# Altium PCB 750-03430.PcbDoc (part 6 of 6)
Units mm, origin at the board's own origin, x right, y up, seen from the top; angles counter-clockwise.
Board outline 141.61 x 63.5 mm, 6 copper layers (Top Layer, L2, L3, L4, L5, Bottom Layer), stack 1.557 mm thick; 401 components, 285 nets, 1356 pads, 1712 vias.
Unrouted connection lines stored in the file: 45.
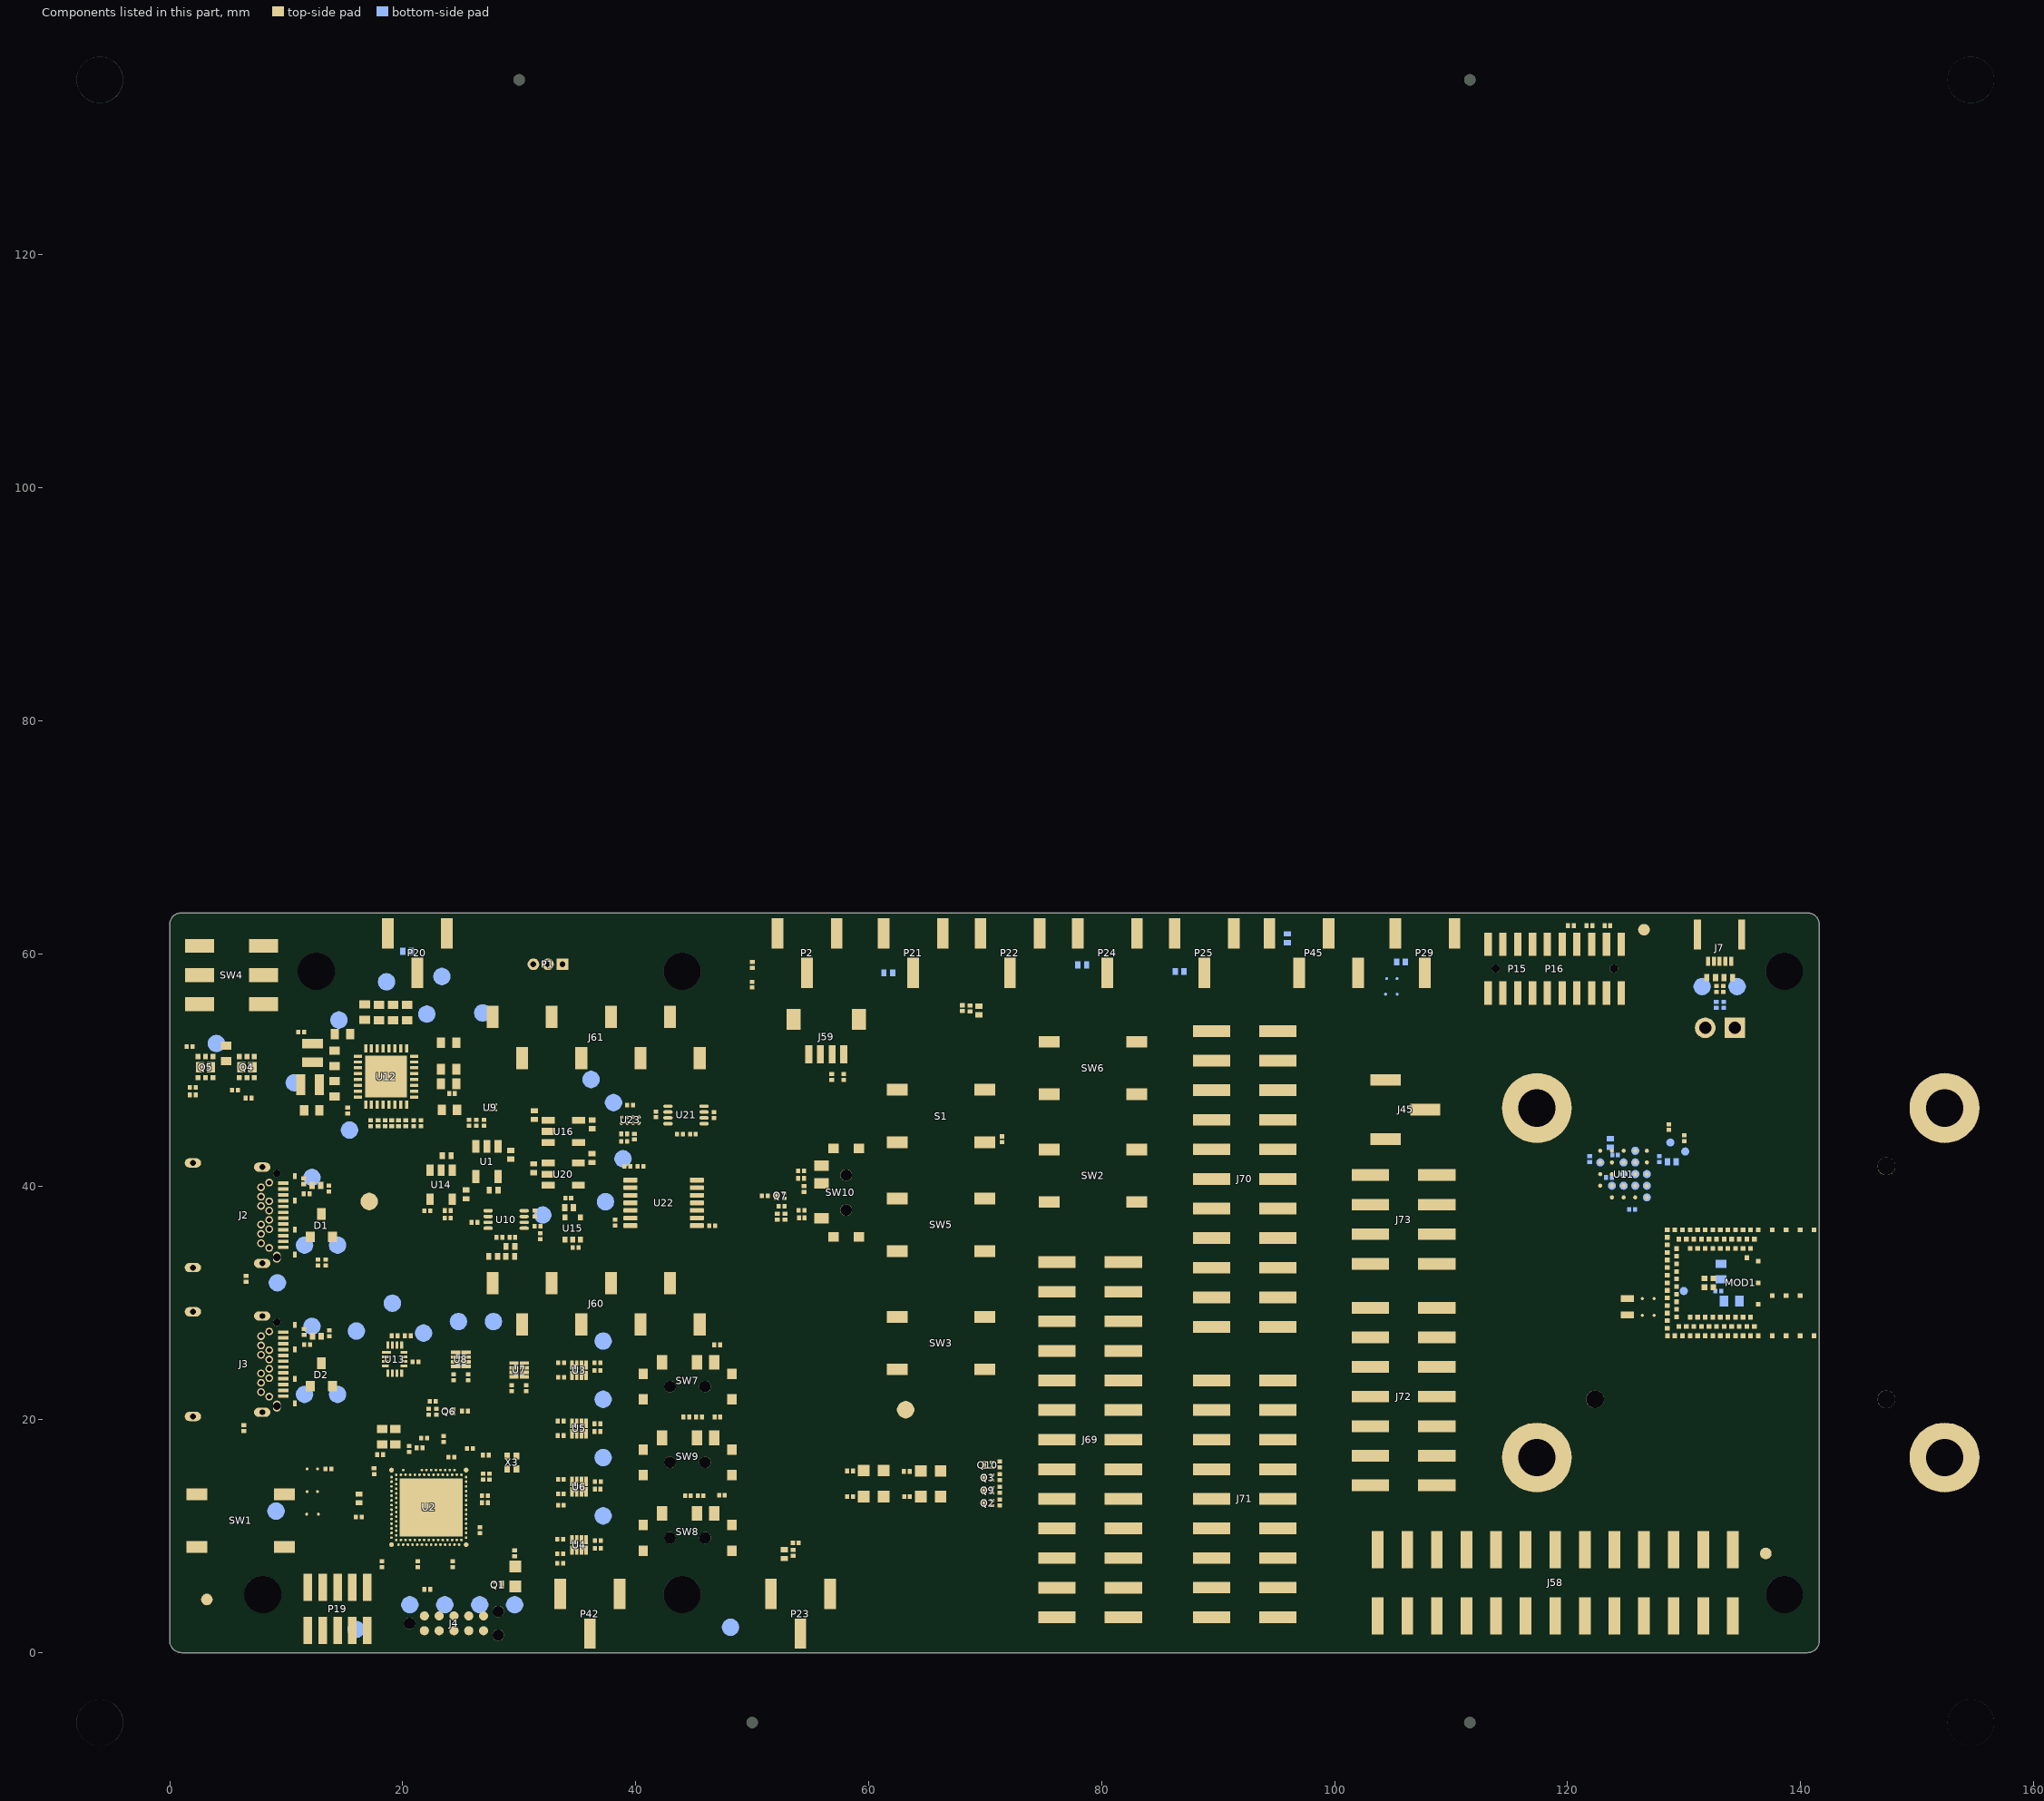
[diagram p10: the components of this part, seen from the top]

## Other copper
Top Layer:
  pour cut-out: 124.322,30.103 124.322,29.303 125.672,29.303 125.672,30.103
  pour cut-out: 112.607,59.562 125.175,59.562 125.175,62.07 112.607,62.07
  region net P3V3: 23.949,39.418 23.949,36.993 24.082,36.861 24.678,36.861 25.74,37.924 25.74,39.192 25.139,39.192 24.913,39.418
  region net P3V3: 33.735,37.118 33.053,37.8 33.053,39 33.262,39.209 34.141,39.209 34.141,37.118
  region net 5V0: 22.649,41.918 22.649,40.671 22.848,40.473 23.744,40.473 23.949,40.678 23.949,43.417 24.146,43.613 24.735,43.613 24.982,43.366 24.982,40.618 24.255,39.891 22.35,39.891 22.049,40.192 22.049,41.918
  region net 5V0: 25.982,44.023 25.982,42.24 26.241,41.981 28.064,41.981 28.975,42.892 29.576,42.892 29.576,43.937 29.49,44.023 27.886,44.023 27.886,42.923 27.601,42.639 26.866,42.639 26.582,42.923 26.582,44.023
  region net 5V0: 33.037,42.327 31.805,42.327 31.06,43.071 30.505,43.071 30.333,42.899 30.333,42.126 30.732,41.727 33.037,41.727
  region net 5V0: 33.046,45.994 30.429,45.994 30.288,45.853 30.288,45.453 30.433,45.309 31.861,45.309 31.946,45.394 33.046,45.394
  region net VBUS_DBGR: 12.776,26.859 12.776,27.461 13.389,27.461 13.501,27.349 13.903,27.349 13.903,26.374 13.747,26.219 13.416,26.219
  region net VBUS_nRF: 12.742,40.411 12.742,39.809 13.356,39.809 13.467,39.921 13.869,39.921 13.869,40.896 13.714,41.052 13.383,41.052
  region net NetC89_2: 11.335,27.447 11.335,27.095 11.575,26.854 12.48,26.854 12.48,27.985 12.379,28.086 12.045,28.086 11.987,28.027 11.987,27.573 11.861,27.447
  region net NetC88_2: 11.298,40.402 11.298,40.05 11.539,39.809 12.444,39.809 12.444,40.94 12.343,41.041 12.009,41.041 11.951,40.983 11.951,40.528 11.824,40.402
  region net VBUS_nRF: 2.141,49.578 2.045,49.482 2.045,47.081 2.132,46.994 2.542,46.994 2.635,47.088 2.635,49.578
  region net VBUS: 3.515,50.938 3.935,50.938 3.935,51.388 4.282,51.735 6.716,51.735 7.064,51.387 7.064,50.937 7.484,50.937 7.484,52.143 6.599,53.028 4.22,53.028 3.515,52.324
  region net NetQ4_3: 5.764,51.387 5.764,50.851 5.795,50.819 5.794,50.818 5.794,49.797 6.844,49.797 7.064,49.577 7.064,49.127 7.484,49.127 7.484,49.669 7.454,49.699 7.454,50.717 6.404,50.717 6.184,50.937 6.184,51.387
  region net VBUS_DBGR: 6.184,49.577 5.764,49.577 5.669,49.482 5.669,47.527 5.861,47.335 6.616,47.335 6.692,47.411 6.692,47.813 6.184,48.321
  region net NetQ5_3: 3.295,49.798 3.515,49.578 3.515,49.128 3.935,49.128 3.935,49.659 3.905,49.689 3.905,50.718 2.876,50.718 2.635,50.959 2.635,51.942 5.762,55.069 9.322,55.069 9.322,56.269 5.313,56.269 1.746,52.702 1.746,50.298 2.245,49.798
  region net VBUS: 23.649,49.565 23.649,50.475 23.649,51.61 22.824,51.61 22.824,50.75 21.909,49.835 20.924,49.835 20.924,49.565
  region net NetC5_1: 20.974,48.564 21.324,48.564 22.006,47.883 22.006,47.115 22.991,46.129 23.702,46.129 23.702,47.043 22.991,47.043 22.602,47.432 22.602,48.022 21.79,48.834 20.974,48.834 20.974,48.699
  region net 5V0: 23.649,49.335 23.649,48.425 23.649,47.235 23.024,47.235 22.824,47.435 22.824,48.15 21.909,49.065 20.924,49.065 20.924,49.335
  region net VOUT2: 11.644,49.657 11.644,47.344 11.894,47.094 11.894,46.093 10.967,46.093 10.844,46.215 10.844,49.657
  region net VOUT1: 13.599,53.665 14.674,53.665 14.874,53.465 14.87,53.461 14.87,52.869 15.124,52.615 15.874,52.615 15.874,53.765 14.86,54.779 12.795,54.779 11.981,53.965 11.374,53.358 11.374,51.875 13.174,51.875 13.174,53.24
  region net PVSS2: 16.174,48.834 15.609,48.834 14.874,48.099 13.692,48.099 13.692,47.618 13.085,47.01 12.504,47.01 12.504,46.097 14.271,46.097 14.674,46.499 14.674,47.374 15.864,48.564 16.174,48.564
  region net 5V0: 15.124,49.85 14.599,50.375 14.599,50.7 13.799,50.7 13.799,48.7 14.599,48.7 14.599,49.025 15.124,49.55
  region net PVSS1: 13.799,53.501 14.574,53.501 14.574,52.926 14.999,52.501 15.624,51.876 15.624,51.076 15.864,50.836 16.174,50.836 16.174,50.566 15.634,50.566 14.899,51.301 13.799,51.301
  pour cut-out: 140.563,30.925 140.563,28.869 140.665,28.869 140.665,28.462 140.563,28.462 140.563,27.295 141.609,27.295 141.609,30.925
  pour cut-out: 129.21,35.977 129.21,35.824 129.262,35.824 129.262,35.977
  pour cut-out: 128.882,34.999 129.035,34.999 129.035,34.947 128.882,34.947
  pour cut-out: 129.86,28.323 129.86,28.503 130.237,28.503 130.237,28.323
  pour cut-out: 129.86,27.523 129.86,27.676 129.912,27.676 129.912,27.523
  pour cut-out: 133.8,27.627 133.8,27.753 133.044,27.753 133.044,27.627
  pour cut-out: 132.081,28.323 132.081,28.476 132.134,28.476 132.134,28.323
  pour cut-out: 134.735,35.177 134.735,35.024 134.787,35.024 134.787,35.177
  pour cut-out: 136.034,35.177 136.034,35.024 135.981,35.024 135.981,35.177
  pour cut-out: 129.035,33.051 128.882,33.051 128.882,33.103 129.035,33.103
  region net NetC29_2: 132.909,28.6 132.909,29.468 133.066,29.625 133.396,29.625 133.538,29.482 133.538,29.229 133.309,29 133.309,28.6
  region net VDD_HV: 133.559,34.9 133.559,34.358 133.44,34.238 133.44,33.922 133.554,33.807 133.969,33.807 134.076,33.914 134.076,34.238 133.959,34.355 133.959,34.9
  text ".layer_Name" at 275.755,-33.955 h2.54
L2:
  pour cut-out: 140.563,30.925 140.563,28.869 140.665,28.869 140.665,28.462 140.563,28.462 140.563,27.295 141.609,27.295 141.609,30.925
  pour cut-out: 136.609,35.925 136.609,30.925 141.609,30.925 141.609,35.925
  pour cut-out: 11.476,11.1 13.021,11.1 13.021,14.841 13.021,16.554 11.476,16.554
  text ".layer_Name" at 275.755,-33.955 h2.54
L3:
  pour cut-out: 140.563,30.925 140.563,28.869 140.665,28.869 140.665,28.462 140.563,28.462 140.563,27.295 141.609,27.295 141.609,30.925
  pour cut-out: 136.609,35.925 136.609,30.925 141.609,30.925 141.609,35.925
  pour cut-out: 11.476,11.1 13.021,11.1 13.021,14.841 13.021,16.554 11.476,16.554
  text ".layer_Name" at 275.755,-33.955 h2.54
L4:
  rectangle net 5V0: 13.917,49.414 15.168,49.981
  pour cut-out: 140.563,30.925 140.563,28.869 140.665,28.869 140.665,28.462 140.563,28.462 140.563,27.295 141.609,27.295 141.609,30.925
  pour cut-out: 136.609,35.925 136.609,30.925 141.609,30.925 141.609,35.925
  text ".layer_Name" at 275.755,-33.955 h2.54
L5:
  pour cut-out: 140.563,30.925 140.563,28.869 140.665,28.869 140.665,28.462 140.563,28.462 140.563,27.295 141.609,27.295 141.609,30.925
  pour cut-out: 136.609,35.925 136.609,30.925 141.609,30.925 141.609,35.925
  text ".layer_Name" at 275.755,-33.955 h2.54
Bottom Layer:
  pour cut-out: 140.563,30.925 140.563,28.869 140.665,28.869 140.665,28.462 140.563,28.462 140.563,27.295 141.609,27.295 141.609,30.925
  pour cut-out: 136.609,35.925 136.609,30.925 141.609,30.925 141.609,35.925
  region net NetC29_2: 133.016,29.206 133.124,29.098 133.482,29.098 133.78,29.396 133.78,30.998 133.524,31.255 133.016,31.255
  text ".layer_Name" at 275.755,-33.955 h2.54

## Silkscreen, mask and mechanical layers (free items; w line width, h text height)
Top Overlay:
  drawing of 92 lines, arcs and shapes, not listed
  text "OFF" at 11.426,61.412 h1.27
  text "NFC" at 136.09,61.387 h1.8
  text "VDD_HV" at 27.234,57.813 h1.4 r90
  text "GND" at 24.198,57.045 h0.64 r90
  text "GND" at 57.66,57.045 h0.64 r90
  text "GND" at 66.767,57.045 h0.64 r90
  text "GND" at 75.081,57.045 h0.64 r90
  text "GND" at 83.44,57.045 h0.64 r90
  text "GND" at 91.754,57.045 h0.64 r90
  text "GND" at 110.696,57.045 h0.64 r90
  text "VDD_P9" at 89.074,55.287 h1.4
  text "P2.01" at 35.665,54.772 h0.7 r90
  text "ON" at 11.505,54.708 h1.27
  text "P2.09" at 40.737,54.681 h0.7 r90
  text "POWER" at 11.014,54.383 h1.8 r90
  text "GND" at 87.61,54.31 h0.64
  text "GND" at 95.705,54.31 h0.64
  text "P2.03" at 30.512,54.196 h0.7 r90
  text "VDD_P1" at 70.997,54.123 h1.4
  text "VDD_P7" at 77.711,54.084 h1.4
  text "VDD_P0" at 61.529,53.95 h1.4
  text "VDD_1V8" at 106.176,53.779 h1.4
  text "P2.02" at 29.312,53.643 h0.7 r90
  text "P2.00" at 34.453,53.619 h0.7 r90
  text "P2.08" at 39.556,53.596 h0.7 r90
  text "DEBUG IN TRACE" at 114.953,52.449 h1.8
  text "P2.01" at 95.673,51.688 h0.64
  text "VDD_HV" at 99.869,51.328 h1.27 r90
  text "VDD_HV'" at 103.411,51.328 h1.27 r90
  text "1V8_LDO" at 102.184,51.23 h1.27 r90
  text "VDD_1V8'" at 101.032,51.196 h1.27 r90
  text "BL54 Reset" at 61.279,49.809 h1.8
  text "P2.00" at 95.673,49.131 h0.64
  text "GND" at 108.292,48.902 h0.64
  text "RX" at 33.186,48.372 h0.7 r90
  text "TX" at 35.726,48.372 h0.7 r90
  text "5V" at 43.346,48.372 h0.7 r90
  text "INT" at 30.646,47.789 h0.7 r90
  text "PWM" at 28.106,47.673 h0.7 r90
  text "SCL" at 38.266,47.673 h0.7 r90
  text "SDA" at 40.806,47.673 h0.7 r90
  text "GND" at 45.886,47.673 h0.7 r90
  text "P2.02" at 95.673,46.608 h0.64
  text "P6.01" at 109.316,46.241 h0.64
  text "Button 3" at 75.072,44.671 h1.8
  text "LED, FLASH PWR LS ON" at 52.133,44.462 h1.52
  text "RXD" at 87.578,44.068 h0.64
  text "P2.04" at 95.673,44.068 h0.64
  text "P6.13" at 107.45,43.695 h0.64
  text "BL54H20 USB" at 0.566,43.608 h1.8
  text "ON" at 54.649,42.057 h0.64 r90
  text "RESET" at 108.948,41.896 h0.64
  text "CTS" at 87.578,41.511 h0.64
  text "P2.05" at 95.673,41.511 h0.64
  text "Button 2" at 62.079,40.492 h1.8
  text "nPM1300" at 14.056,40.032 h1.8
  text "SWDIO" at 108.948,39.371 h0.64
  text "TXD" at 87.578,38.979 h0.64
  text "P2.06" at 95.673,38.979 h0.64
  text "SWD" at 100.319,37.297 h0.89 r90
  text "UART0" at 86.433,37.268 h0.89 r90
  text "SWDCLK" at 108.948,36.746 h0.64
  text "RTS" at 87.578,36.364 h0.64
  text "P2.07" at 95.673,36.364 h0.64
  text "Button 0" at 75.203,35.639 h1.8
  text "GND" at 16.307,35.561 h1.4
  text "OFF" at 54.695,34.965 h0.64 r90
  text "GND" at 81.885,34.381 h0.64
  text "GND" at 73.602,34.322 h0.64
  text "GND" at 108.948,34.238 h0.64
  text "RX" at 87.578,33.899 h0.64
  text "P2.09" at 95.673,33.899 h0.64
  text "SCK" at 36.694,33.204 h0.7 r90
  text "MOSI" at 40.766,33.203 h0.7 r90
  text "MISO" at 38.226,33.177 h0.7 r90
  text "3V3" at 43.306,33.154 h0.7 r90
  text "GND" at 45.846,33.159 h0.7 r90
  text "CS" at 33.146,33.115 h0.7 r90
  text "UI0" at 73.602,31.92 h0.64
  text "AN" at 29.361,31.847 h0.7 r90
  text "P0.08" at 81.885,31.845 h0.64
  text "RST" at 30.705,31.378 h0.7 r90
  text "TX" at 87.578,31.284 h0.64
  text "P2.08" at 95.673,31.284 h0.64
  text "Button 1" at 62.079,30.645 h1.8
  text "P9.05" at 109.263,30.512 h0.64
  text "DEBUGGER" at 0.389,29.83 h1.8
  text "MK_UART" at 86.181,29.827 h0.64 r90
  text "UI3" at 73.602,29.363 h0.64
  text "P0.11" at 81.885,29.32 h0.64
  text "INT" at 87.684,28.742 h0.64
  text "P2.03" at 95.673,28.742 h0.64
  text "P9.04" at 109.263,27.987 h0.64
  text "UI2" at 73.602,26.831 h0.64
  text "P0.10" at 81.902,26.811 h0.64
  text "OFF" at 47.767,26.123 h0.64
  text "ON" at 40.618,26.093 h0.64
  text "P1.01" at 29.421,25.509 h0.64 r90
  text "P7.00" at 34.518,25.475 h0.64 r90
  text "P9.00" at 109.263,25.432 h0.64
  text "P7.02" at 39.57,25.415 h0.64 r90
  text "UI0" at 101.323,25.38 h0.64
  text "MK" at 86.247,25.107 h0.89 r90
  text "PWM" at 86.826,25.039 h0.64
  text "P1.02" at 32.85,24.895 h0.64 r90
  text "P7.01" at 38.301,24.823 h0.64 r90
  text "Button" at 72.762,24.728 h0.89 r90
  text "P1.00" at 28.243,24.572 h0.64 r90
  text "UI1" at 73.602,24.212 h0.64
  text "P0.09" at 81.855,24.216 h0.64
  text "SWD0 LS" at 49.067,24.191 h1.8
  text "DATA1" at 86.804,24.145 h0.64
  text "P7.05" at 95.673,24.148 h0.64
  text "MOD1" at 126.391,23.757 h1.8
  text "P9.02" at 109.263,22.907 h0.64
  text "UI2" at 101.323,22.856 h0.64
  text "P0.05" at 81.885,21.685 h0.64
  text "P7.07" at 95.673,21.673 h0.64
  text "DATA3" at 86.826,21.473 h0.64
  text "P9.01" at 109.263,20.398 h0.64
  text "UI1" at 101.535,20.231 h0.64
  text "GND" at 64.431,19.872 h1.4
  text "OFF" at 47.942,19.753 h0.64
  text "ON" at 40.686,19.686 h0.64
  text "P0.07" at 81.885,19.16 h0.64
  text "LEDS" at 100.249,19.132 h0.89 r90
  text "DATA2" at 87.023,19.122 h0.64
  text "P7.06" at 95.673,19.122 h0.64
  text "Debugger" at 24.556,18.048 h1.8
  text "P9.03" at 109.263,17.803 h0.64
  text "UI3" at 101.323,17.646 h0.64
  text "UART1 LS" at 49.071,17.573 h1.8
  text "LED1" at 58.357,17.328 h1.14
  text "LED3" at 63.574,17.328 h1.14
  text "P0.06" at 81.902,16.651 h0.64
  text "CLK" at 88.293,16.587 h0.64
  text "P7.03" at 95.639,16.587 h0.64
  text "Trace" at 86.227,16.507 h0.89 r90
  text "RESET" at 3.223,15.375 h1.8
  text "GND" at 109.263,15.223 h0.64
  text "GND" at 101.217,15.163 h0.64
  text "DATA0" at 87.039,14.112 h0.64
  text "P0.01" at 81.722,14.067 h0.64
  text "P7.04" at 95.673,14.061 h0.64
  text "ON" at 40.68,13.144 h0.64
  text "OFF" at 48.157,13.114 h0.64
  text "CS" at 86.418,12.215 h0.64
  text "P0.02" at 81.885,11.525 h0.64
  text "P7.01" at 95.673,11.513 h0.64
  text "MOSI" at 87.885,11.423 h0.64
  text "LED2" at 58.357,10.525 h1.14
  text "LED0" at 63.574,10.525 h1.14
  text "UART0 LS" at 49.133,10.462 h1.8
  text "P0.03" at 81.885,9 h0.64
  text "P7.02" at 95.673,8.981 h0.64
  text "CLK" at 88.308,8.933 h0.64
  text "P1.11" at 102.824,8.816 h0.64 r90
  text "P1.10" at 105.349,8.816 h0.64 r90
  text "P1.09" at 107.858,8.816 h0.64 r90
  text "P1.07" at 110.453,8.816 h0.64 r90
  text "P1.08" at 112.983,8.815 h0.64 r90
  text "P1.06" at 115.508,8.815 h0.64 r90
  text "P1.05" at 118.017,8.815 h0.64 r90
  text "P1.04" at 120.612,8.815 h0.64 r90
  text "P1.00" at 125.795,8.815 h0.64 r90
  text "P1.01" at 128.32,8.815 h0.64 r90
  text "GND" at 133.393,8.815 h0.64 r90
  text "P1.03" at 123.21,8.805 h0.64 r90
  text "P1.02" at 130.772,8.764 h0.64 r90
  text "MK_SPI" at 86.422,6.761 h0.89 r90
  text "750-03430-R3.0" at 60.111,6.716 h1.65
  text "P0.00" at 81.902,6.491 h0.64
  text "P7.00" at 95.673,6.368 h0.64
  text "MISO" at 87.779,6.335 h0.64
  text "VDD_SWDO" at 32.394,6.038 h1.52 r90
  text "DVK-BL54H20" at 59.674,5.233 h1.65
  text "P0.04" at 81.855,3.896 h0.64
  text "GND" at 88.293,3.808 h0.64
  text "GND" at 95.676,3.808 h0.64
  text "AN" at 125.705,1.947 h0.64 r90
  text "SCL" at 123.246,1.799 h0.64 r90
  text "SDA" at 120.615,1.749 h0.64 r90
  text "TXD" at 102.724,1.312 h0.64 r90
  text "RXD" at 105.281,1.312 h0.64 r90
  text "RTS" at 107.813,1.312 h0.64 r90
  text "CTS" at 110.432,1.312 h0.64 r90
  text "RST" at 128.245,1.312 h0.64 r90
  text "UART1" at 97.332,1.195 h0.89
  text "MK" at 138.001,1.094 h0.64
  text "VDD_P2" at 49.896,0.618 h1.4 r90
  text "I2C" at 121.922,0.604 h0.64
  text "DEBUG OUT" at 2.116,0.355 h1.8
  text "GND" at 38.932,0.209 h0.64 r90
  text ".layer_Name" at 275.755,-33.955 h2.54
Bottom Overlay:
  text ".layer_Name" at 275.755,-33.955 h2.54
Top Paste:
  text ".layer_Name" at 275.755,-33.955 h2.54
Bottom Paste:
  text ".layer_Name" at 275.755,-33.955 h2.54
Top Solder:
  region: 140.959,27 140.959,27.295 140.908,27.295 140.908,27.451 141.41,27.451 141.41,27 141.359,27
  region: 140.959,27.4 141.254,27.4 141.254,27.451 141.41,27.451 141.41,26.949 141.35,26.949 141.35,27 140.959,27
  text ".layer_Name" at 275.755,-33.955 h2.54
Bottom Solder:
  text ".layer_Name" at 275.755,-33.955 h2.54
Board Outline:
  lines w0.254: 0,62.482 cw(c1.016,62.482) 1.016,63.498 ; 0,62.484 0,1.016 ccw(c1.016,1.016) 1.016,0 140.593,0 ccw(c140.593,1.016) 141.609,1.016 141.609,62.484 ccw(c140.593,62.484) 140.593,63.5 1.02,63.5
Top Title Block:
  drawing of 49 lines, arcs and shapes, not listed
  text "DATE" at 367.388,235.868 h1.78
  text "ENG." at 381.993,235.639 h1.78
  text "REV." at 271.528,235.614 h1.78
  text "DESCRIPTION" at 306.86,235.614 h1.78
  text "1.0" at 271.558,231.69 h1.78
  text "Sep 13, 2023" at 362.245,231.69 h1.78
  text "Initial release" at 279.658,231.605 h1.78
  text "2.0" at 271.559,227.502 h1.78
  text "Jun 18, 2024" at 362.246,227.502 h1.78
  text "DVT1" at 279.659,227.418 h1.78
  text "3.0" at 271.56,223.315 h1.78
  text "Oct 15, 2024" at 362.248,223.315 h1.78
  text "Add R121, R122 and R123" at 279.66,223.23 h1.78
  text "APPROVALS" at 278.295,0.335 h1.78
  text "DATE" at 306.235,0.335 h1.78
  text "DRAWN:" at 270.675,-4.745 h1.27
  text ".ProjectDrawnBy" at 283.375,-4.745 h1.27
  text ".ProjectDrawnDate" at 303.695,-4.745 h1.27
  text ".ProjectAddress1" at 359.575,-4.745 h1.52
  text ".ProjectAddress2" at 359.575,-7.285 h1.52
  text "CHECKED:" at 270.675,-9.825 h1.27
  text ".ProjectCheckedBy" at 283.375,-9.825 h1.27
  text ".ProjectCheckedDate" at 303.695,-9.825 h1.27
  text "Phone: .ProjectPhone" at 359.575,-9.825 h1.52
  text "www.ezurio.com" at 359.575,-12.365 h1.52
  text "APPROVED:" at 270.675,-14.905 h1.27
  text ".ProjectApprovedBy" at 283.375,-14.905 h1.27
  text ".ProjectApprovedDate" at 303.695,-14.905 h1.27
  text "Title:" at 270.222,-20.056 h1.27
  text "PCB, .ProjectTitle" at 273.722,-24.856 h3.81
  text ", Chip Antenna" at 361.638,-25.083 h3.81
  text "Layer:" at 270.722,-29.956 h1.27
  text "Project:" at 322.745,-30.145 h1.27
  text "DWG NO." at 350.685,-30.145 h1.27
  text "REV:" at 382.435,-30.145 h1.27
  text ".ProjectPCBRevision" at 382.435,-32.685 h1.78
  text "'.ProjectPCBNumber'" at 357.543,-33.61 h1.78
  text ".ProjectNumber" at 329.095,-33.955 h1.52
  text "Customer: .ProjectCustomerName" at 303.695,-37.765 h1.27
  text "Last Modified:" at 324.015,-37.765 h1.27
  text "SIZE:" at 350.685,-37.765 h1.27
  text "SCALE:" at 360.337,-37.765 h1.27
  text "SHEET:" at 372.275,-37.765 h1.27
  text "File:" at 270.268,-37.878 h1.27
  text ".PCB_File_Name_No_Path" at 272.422,-39.956 h1.27
  text "'.Print_Date'" at 324.015,-40.305 h1.27
  text ".Print_Time" at 335.445,-40.305 h1.27
  text "1:1" at 362.115,-40.813 h1.27
  text "1 OF 1" at 375.831,-40.813 h1.27
  text "B" at 351.701,-41.829 h3.05
Top Assembly (Mech13):
  text ".layer_Name" at 275.755,-33.955 h2.54
Bottom Assembly (Mech14):
  text ".layer_Name" at 275.755,-33.955 h2.54
Drill Drawing:
  drawing of 264 lines, arcs and shapes, not listed
  text "PCB NOTES:" at 205.903,187.993 h3.97
  text "1. Thickness: 1.6mm, Tolerance+/-0.1mm / 2. Impedance= (1) RF 50 ohm, Traces-TOP/L3 Layer ref to L2/L2, L4 Layer, Trace Width 5/4mil. /   Differential = (2) 90 ohm, Traces-TOP/ BOT Layer ref to L2/ L5 Layer, Trace Width 4.7mil, Spacing 4mil / 3. Please refer to the \"PCB SPECIFICATION SHEET\" for details." at 205.277,170.262 h1.52
  text "Symbol" at 201.704,153.404 h1.83
  text "Count" at 214.553,153.404 h1.83
  text "Hole Size" at 231.059,153.404 h1.83
  text "Plated" at 260.26,153.404 h1.83
  text "Hole Type" at 273.109,153.404 h1.83
  text "Drill Layer Pair" at 291.748,153.404 h1.83
  text "Via/Pad" at 329.836,153.404 h1.83
  text "Pad Shape" at 344.819,153.404 h1.83
  text "223" at 214.553,149.594 h1.52
  text "7.87mil (0.200mm)" at 231.059,149.594 h1.52
  text "PTH" at 260.26,149.594 h1.52
  text "Round" at 273.109,149.594 h1.52
  text "Top Layer - Bottom Layer" at 291.748,149.594 h1.52
  text "Via" at 329.836,149.594 h1.52
  text "Rounded" at 344.819,149.594 h1.52
  text "1306" at 214.553,145.784 h1.52
  text "9.84mil (0.250mm)" at 231.059,145.784 h1.52
  text "PTH" at 260.26,145.784 h1.52
  text "Round" at 273.109,145.784 h1.52
  text "Top Layer - Bottom Layer" at 291.748,145.784 h1.52
  text "Via" at 329.836,145.784 h1.52
  text "Rounded" at 344.819,145.784 h1.52
  text "16" at 214.553,141.974 h1.52
  text "12.00mil (0.305mm)" at 231.059,141.974 h1.52
  text "PTH" at 260.26,141.974 h1.52
  text "Round" at 273.109,141.974 h1.52
  text "Top Layer - Bottom Layer" at 291.748,141.974 h1.52
  text "Via" at 329.836,141.974 h1.52
  text "Rounded" at 344.819,141.974 h1.52
  text "9" at 214.553,138.164 h1.52
  text "12.01mil (0.305mm)" at 231.059,138.164 h1.52
  text "PTH" at 260.26,138.164 h1.52
  text "Round" at 273.109,138.164 h1.52
  text "Top Layer - Bottom Layer" at 291.748,138.164 h1.52
  text "Via" at 329.836,138.164 h1.52
  text "Rounded" at 344.819,138.164 h1.52
  text "24" at 214.553,134.354 h1.52
  text "15.75mil (0.400mm)" at 231.059,134.354 h1.52
  text "PTH" at 260.26,134.354 h1.52
  text "Round" at 273.109,134.354 h1.52
  text "Top Layer - Bottom Layer" at 291.748,134.354 h1.52
  text "Pad" at 329.836,134.354 h1.52
  text "Rounded" at 344.819,134.354 h1.52
  text "A" at 200.965,134.1 h1.69
  text "3" at 214.553,130.544 h1.52
  text "19.69mil (0.500mm)" at 231.059,130.544 h1.52
  text "PTH" at 260.26,130.544 h1.52
  text "Round" at 273.109,130.544 h1.52
  text "Top Layer - Bottom Layer" at 291.748,130.544 h1.52
  text "Pad" at 329.836,130.544 h1.52
  text "(Mixed)" at 344.819,130.544 h1.52
  text "G" at 200.965,130.29 h1.69
  text "8" at 214.553,126.734 h1.52
  text "19.69mil (0.500mm)" at 231.059,126.734 h1.52
  text "PTH" at 260.26,126.734 h1.52
  text "Slot" at 273.109,126.734 h1.52
  text "Top Layer - Bottom Layer" at 291.748,126.734 h1.52
  text "Pad" at 329.836,126.734 h1.52
  text "Rounded" at 344.819,126.734 h1.52
  text "B" at 200.965,126.48 h1.69
  text "2" at 214.553,122.924 h1.52
  text "25.59mil (0.650mm)" at 231.059,122.924 h1.52
  text "NPTH" at 260.26,122.924 h1.52
  text "Round" at 273.109,122.924 h1.52
  text "Top Layer - Bottom Layer" at 291.748,122.924 h1.52
  text "Pad" at 329.836,122.924 h1.52
  text "Rounded" at 344.819,122.924 h1.52
  text "C" at 200.965,122.67 h1.69
  text "2" at 214.553,119.114 h1.52
  text "25.59mil (0.650mm)" at 231.059,119.114 h1.52
  text "NPTH" at 260.26,119.114 h1.52
  text "Slot" at 273.109,119.114 h1.52
  text "Top Layer - Bottom Layer" at 291.748,119.114 h1.52
  text "Pad" at 329.836,119.114 h1.52
  text "Rounded" at 344.819,119.114 h1.52
  text "D" at 200.965,118.86 h1.69
  text "2" at 214.553,115.304 h1.52
  text "27.56mil (0.700mm)" at 231.059,115.304 h1.52
  text "NPTH" at 260.26,115.304 h1.52
  text "Round" at 273.109,115.304 h1.52
  text "Top Layer - Bottom Layer" at 291.748,115.304 h1.52
  text "Pad" at 329.836,115.304 h1.52
  text "Rounded" at 344.819,115.304 h1.52
  text "3" at 214.553,111.494 h1.52
  text "39.00mil (0.991mm)" at 231.059,111.494 h1.52
  text "NPTH" at 260.26,111.494 h1.52
  text "Round" at 273.109,111.494 h1.52
  text "Top Layer - Bottom Layer" at 291.748,111.494 h1.52
  text "Pad" at 329.836,111.494 h1.52
  text "Rounded" at 344.819,111.494 h1.52
  text "8" at 214.553,107.684 h1.52
  text "39.37mil (1.000mm)" at 231.059,107.684 h1.52
  text "NPTH" at 260.26,107.684 h1.52
  text "Round" at 273.109,107.684 h1.52
  text "Top Layer - Bottom Layer" at 291.748,107.684 h1.52
  text "Pad" at 329.836,107.684 h1.52
  text "Rounded" at 344.819,107.684 h1.52
  text "2" at 214.553,103.874 h1.52
  text "42.00mil (1.067mm)" at 231.059,103.874 h1.52
  text "PTH" at 260.26,103.874 h1.52
  text "Round" at 273.109,103.874 h1.52
  text "Top Layer - Bottom Layer" at 291.748,103.874 h1.52
  text "Pad" at 329.836,103.874 h1.52
  text "Rounded" at 344.819,103.874 h1.52
  text "3" at 214.553,100.064 h1.52
  text "60.00mil (1.524mm)" at 231.059,100.064 h1.52
  text "NPTH" at 260.26,100.064 h1.52
  text "Round" at 273.109,100.064 h1.52
  text "Top Layer - Bottom Layer" at 291.748,100.064 h1.52
  text "Pad" at 329.836,100.064 h1.52
  text "Rounded" at 344.819,100.064 h1.52
  text "4" at 214.553,96.254 h1.52
  text "125.98mil (3.200mm)" at 231.059,96.254 h1.52
  text "NPTH" at 260.26,96.254 h1.52
  text "Round" at 273.109,96.254 h1.52
  text "Top Layer - Bottom Layer" at 291.748,96.254 h1.52
  text "Pad" at 329.836,96.254 h1.52
  text "Rounded" at 344.819,96.254 h1.52
  text "6" at 214.553,92.444 h1.52
  text "126.00mil (3.200mm)" at 231.059,92.444 h1.52
  text "NPTH" at 260.26,92.444 h1.52
  text "Round" at 273.109,92.444 h1.52
  text "Top Layer - Bottom Layer" at 291.748,92.444 h1.52
  text "Pad" at 329.836,92.444 h1.52
  text "Rounded" at 344.819,92.444 h1.52
  text "4" at 214.553,88.634 h1.52
  text "157.48mil (4.000mm)" at 231.059,88.634 h1.52
  text "NPTH" at 260.26,88.634 h1.52
  text "Round" at 273.109,88.634 h1.52
  text "Top Layer - Bottom Layer" at 291.748,88.634 h1.52
  text "Pad" at 329.836,88.634 h1.52
  text "Rounded" at 344.819,88.634 h1.52
  text "Symbol" at 201.704,87.365 h1.83
  text "Symbol" at 201.704,87.365 h1.83
  text "Count" at 214.553,87.365 h1.83
  text "Count" at 214.553,87.365 h1.83
  text "Hole Size" at 228.012,87.365 h1.83
  text "Hole Size" at 229.281,87.365 h1.83
  text "Plated" at 254.166,87.365 h1.83
  text "Plated" at 255.436,87.365 h1.83
  text "Hole Type" at 267.015,87.365 h1.83
  text "Hole Type" at 268.285,87.365 h1.83
  text "Drill Layer Pair" at 285.654,87.365 h1.83
  text "Drill Layer Pair" at 286.923,87.365 h1.83
  text "Via/Pad" at 315.871,87.365 h1.83
  text "Via/Pad" at 317.141,87.365 h1.83
  text "Pad Shape" at 330.853,87.365 h1.83
  text "Pad Shape" at 332.123,87.365 h1.83
  text "1625 Total" at 214.553,84.824 h1.52
  text "41" at 214.553,83.555 h1.52
  text "117" at 214.553,83.555 h1.52
  text "3.94mil (0.100mm)" at 228.012,83.555 h1.52
  text "3.94mil (0.100mm)" at 229.281,83.555 h1.52
  text "PTH" at 254.166,83.555 h1.52
  text "PTH" at 255.436,83.555 h1.52
  text "Round" at 267.015,83.555 h1.52
  text "Round" at 268.285,83.555 h1.52
  text "Top Layer - L2" at 285.654,83.555 h1.52
  text "Top Layer - L3" at 286.923,83.555 h1.52
  text "Via" at 315.871,83.555 h1.52
  text "Via" at 317.141,83.555 h1.52
  text "Rounded" at 330.853,83.555 h1.52
  text "Rounded" at 332.123,83.555 h1.52
  text "Slot definitions :" at 201.704,81.142 h1.52
  text "Routed Path Length" at 227.934,81.142 h1.52
  text "= Calculated from tool start centre position to tool end centre position." at 255.942,81.142 h1.52
  text "41 Total" at 214.553,79.745 h1.52
  text "117 Total" at 214.553,79.745 h1.52
  text "Hole Length" at 227.934,78.602 h1.52
  text "= Routed Path Length + Tool Size = Slot length as defined in the PCB layout" at 245.531,78.602 h1.52
  text "Layer" at 204.821,61.27 h1.52
  text "Name" at 215.233,61.27 h1.52
  text "Material" at 238.849,61.27 h1.52
  text "Thickness" at 254.085,61.27 h1.52
  text "Constant" at 270.591,61.27 h1.52
  text "Top Overlay" at 215.233,58.222 h1.52
  text "Top Solder" at 215.233,55.174 h1.52
  text "SM-003" at 238.849,55.174 h1.52
  text "0.40mil" at 254.085,55.174 h1.52
  text "3.5" at 270.591,55.174 h1.52
  text "1" at 204.821,52.126 h1.52
  text "Top Layer" at 215.233,52.126 h1.52
  text "CF-002" at 238.849,52.126 h1.52
  text "1.89mil" at 254.085,52.126 h1.52
  text "Dielectric 1" at 215.233,49.078 h1.52
  text "PP-010" at 238.849,49.078 h1.52
  text "3.31mil" at 254.085,49.078 h1.52
  text "4" at 270.591,49.078 h1.52
  text "2" at 204.821,46.03 h1.52
  text "L2" at 215.233,46.03 h1.52
  text "CF-002" at 238.849,46.03 h1.52
  text "1.18mil" at 254.085,46.03 h1.52
  text "Dielectric 2" at 215.233,42.982 h1.52
  text "PP-010" at 238.849,42.982 h1.52
  text "3.19mil" at 254.085,42.982 h1.52
  text "4" at 270.591,42.982 h1.52
  text "3" at 204.821,39.934 h1.52
  text "L3" at 215.233,39.934 h1.52
  text "CF-002" at 238.849,39.934 h1.52
  text "1.58mil" at 254.085,39.934 h1.52
  text "Dielectric 3" at 215.233,36.886 h1.52
  text "Core-042" at 238.849,36.886 h1.52
  text "39.02mil" at 254.085,36.886 h1.52
  text "4.6" at 270.591,36.886 h1.52
  text "4" at 204.821,33.838 h1.52
  text "L4" at 215.233,33.838 h1.52
  text "CF-002" at 238.849,33.838 h1.52
  text "1.58mil" at 254.085,33.838 h1.52
  text "Dielectric 4" at 215.233,30.79 h1.52
  text "PP-010" at 238.849,30.79 h1.52
  text "3.19mil" at 254.085,30.79 h1.52
  text "4" at 270.591,30.79 h1.52
  text "5" at 204.821,27.742 h1.52
  text "L5" at 215.233,27.742 h1.52
  text "CF-002" at 238.849,27.742 h1.52
  text "1.18mil" at 254.085,27.742 h1.52
  text "Dielectric 5" at 215.233,24.694 h1.52
  text "PP-010" at 238.849,24.694 h1.52
  text "3.31mil" at 254.085,24.694 h1.52
  text "4" at 270.591,24.694 h1.52
  text "6" at 204.821,21.646 h1.52
  text "Bottom Layer" at 215.233,21.646 h1.52
  text "CF-002" at 238.849,21.646 h1.52
  text "1.89mil" at 254.085,21.646 h1.52
  text "Bottom Solder" at 215.233,18.598 h1.52
  text "SM-003" at 238.849,18.598 h1.52
  text "0.40mil" at 254.085,18.598 h1.52
  text "3.5" at 270.591,18.598 h1.52
  text "Bottom Overlay" at 215.233,15.55 h1.52
Panel:
  lines w0.254: -1.996,13.22 cw(c-0.998,13.22) -0.998,14.218 cw(c-0.998,13.22) -0.001,13.22 ; -1.996,17.215 ccw(c-0.998,17.215) -0.998,16.218 ccw(c-0.998,17.215) -0.001,17.215 ; -1.996,46.285 cw(c-0.998,46.285) -0.998,47.282 cw(c-0.998,46.285) -0.001,46.285 ; -1.996,50.28 ccw(c-0.998,50.28) -0.998,49.282 ccw(c-0.998,50.28) -0.001,50.28 ; -1.996,78.72 cw(c-0.998,78.72) -0.998,79.718 cw(c-0.998,78.72) -0.001,78.72 ; -1.996,82.715 ccw(c-0.998,82.715) -0.998,81.718 ccw(c-0.998,82.715) -0.001,82.715 ; -1.996,111.785 cw(c-0.998,111.785) -0.998,112.782 cw(c-0.998,111.785) -0.001,111.785 ; -1.996,115.78 ccw(c-0.998,115.78) -0.998,114.782 ccw(c-0.998,115.78) -0.001,115.78 ; 15.206,-1.995 ccw(c15.206,-0.998) 16.204,-0.998 ccw(c15.206,-0.998) 15.206,0 ; 15.206,63.505 ccw(c15.206,64.502) 16.204,64.502 ccw(c15.206,64.502) 15.206,65.5 ; 15.206,129.005 ccw(c15.206,130.002) 16.204,130.002 ccw(c15.206,130.002) 15.206,131 ; 19.202,-1.995 cw(c19.202,-0.998) 18.204,-0.998 cw(c19.202,-0.998) 19.202,0 ; 19.202,63.505 cw(c19.202,64.502) 18.204,64.502 cw(c19.202,64.502) 19.202,65.5 ; 19.201,129.005 cw(c19.201,130.002) 18.204,130.002 cw(c19.201,130.002) 19.201,131 ; 68.809,-1.998 ccw(c68.809,-1) 69.807,-1 ccw(c68.809,-1) 68.809,-0.002 ; 68.809,63.502 ccw(c68.809,64.5) 69.807,64.5 ccw(c68.809,64.5) 68.809,65.498 ; 68.809,129.002 ccw(c68.809,130) 69.807,130 ccw(c68.809,130) 68.809,130.998 ; 72.804,-1.998 cw(c72.804,-1) 71.807,-1 cw(c72.804,-1) 72.804,-0.002 ; 72.804,63.502 cw(c72.804,64.5) 71.807,64.5 cw(c72.804,64.5) 72.804,65.498 ; 72.804,129.002 cw(c72.804,130) 71.807,130 cw(c72.804,130) 72.804,130.998 ; 122.407,-1.994 ccw(c122.407,-0.996) 123.405,-0.996 ccw(c122.407,-0.996) 122.407,0.002 ; 122.407,63.506 ccw(c122.407,64.504) 123.405,64.504 ccw(c122.407,64.504) 122.407,65.501 ; 122.407,129.006 ccw(c122.407,130.004) 123.405,130.004 ccw(c122.407,130.004) 122.407,131.001 ; 126.403,-1.994 cw(c126.403,-0.996) 125.405,-0.996 cw(c126.403,-0.996) 126.403,0.002 ; 126.403,63.506 cw(c126.403,64.504) 125.405,64.504 cw(c126.403,64.504) 126.403,65.501 ; 126.403,129.006 cw(c126.403,130.004) 125.405,130.004 cw(c126.403,130.004) 126.403,131.001 ; 141.614,13.22 cw(c142.612,13.22) 142.612,14.218 cw(c142.612,13.22) 143.609,13.22 ; 141.614,17.215 ccw(c142.612,17.215) 142.612,16.218 ccw(c142.612,17.215) 143.609,17.215 ; 141.614,46.285 cw(c142.612,46.285) 142.612,47.282 cw(c142.612,46.285) 143.609,46.285 ; 141.614,50.28 ccw(c142.612,50.28) 142.612,49.282 ccw(c142.612,50.28) 143.609,50.28 ; 141.614,78.72 cw(c142.611,78.72) 142.611,79.718 cw(c142.611,78.72) 143.609,78.72 ; 141.614,82.715 ccw(c142.611,82.715) 142.611,81.718 ccw(c142.611,82.715) 143.609,82.715 ; 141.614,111.785 cw(c142.611,111.785) 142.611,112.782 cw(c142.611,111.785) 143.609,111.785 ; 141.614,115.78 ccw(c142.611,115.78) 142.611,114.782 ccw(c142.611,115.78) 143.609,115.78 ; -9.996,-10 158.609,-10 158.609,139 -9.996,139 -9.996,-10 ; -1.996,-2 -1.996,131 143.609,131 143.609,-2 -1.996,-2 ; 0.004,1.016 ccw(c1.02,1.016) 1.02,0 140.593,0 ccw(c140.593,1.016) 141.609,1.016 141.609,62.484 ccw(c140.593,62.484) 140.593,63.5 1.02,63.5 ccw(c1.02,62.484) 0.004,62.484 0.004,1.016 ; 0.004,66.516 ccw(c1.02,66.516) 1.02,65.5 140.593,65.5 ccw(c140.593,66.516) 141.609,66.516 141.609,127.984 ccw(c140.593,127.984) 140.593,129 1.02,129 ccw(c1.02,127.984) 0.004,127.984 0.004,66.516
  text ".layer_Name" at 275.755,-33.955 h2.54

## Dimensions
1.02,65.5 to 1.02,129 on Top Via Capping
0,1.025 to -0.058,-11.995 on Top Via Capping
140.589,0.001 to 160.795,-0.033 on Top Via Capping
140.589,63.501 to 160.795,63.467 on Top Via Capping
140.589,65.501 to 160.795,65.467 on Top Via Capping
141.609,1.016 to 141.551,-12.004 on Top Via Capping
-9.996,139 to 158.609,139 on Top Via Capping
0.004,127.984 to 141.609,127.984 on Top Via Capping
-9.996,139 to -1.996,131 on Top Via Capping
-1.996,131 to -9.996,139 on Top Via Capping
-1.996,131 to 1.02,129 on Top Via Capping
-1.996,131 to 0.004,127.984 on Top Via Capping
-9.996,-10 to -9.996,139 on Top Via Capping
140.589,129.001 to 160.795,128.967 on Top Via Capping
